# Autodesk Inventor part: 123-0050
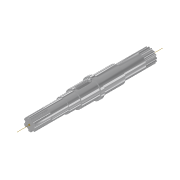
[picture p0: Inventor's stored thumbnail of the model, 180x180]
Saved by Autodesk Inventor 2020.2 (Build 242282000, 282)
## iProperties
+MSCProtocol1+ProtocolID: P00060228124250375
+MSCProtocol2+Protocol: P00060228124250375<@PID>[Version]<@EL>Version=2.0<@EL>[CalcData]<@EL>LastID=8<@EL>Gen=3<@EL>IsMCW=0<@EL>CalcResult=False<@EL>[Files]<@EL>DataFile=SpiData|shaft3
Manager: www.cadconsulting.pl
Company: Fabian Stasiak CAD Consulting
Created: 2004-04
Part Number: 123-0050
Document SubType Name: Modeling
Manufacturer: Standard
Standards Organization: Custom
Description: Wałek
Material: Stal 45
Project: Przekładnia X51
Designer: F.Stasiak
Density: 7.85 g/cm^3
Appearance: Chrom
+MSCFeatProtocols1+FeatNameP00060309102124484: SPLINE2A2
+MSCFeatProtocols2+ProtocolIDP00060309102124484: P00060309102124484
+MSCFeatProtocols3+ProtocolP00060309102124484: P00060309102124484<@PID>[Version]<@EL>Version=2.2<@EL>[Object]<@EL>Description=Kreator wielowypustów ewolwentowych<@EL>ProtID=<@EL>Object=SPLINE2<@EL>[Synchroni
+MSCFeatProtocols4+FeatNameP00060309103342671: N014942B1
+MSCFeatProtocols5+ProtocolIDP00060309103342671: P00060309103342671
+MSCFeatProtocols6+ProtocolP00060309103342671: P00060309103342671<@PID>[Version]<@EL>Version=2.2<@EL>[Synchronize]<@EL>ChangedVars=<@EL>[Calc]<@EL>WizardMode=0<@EL>Version=10.3.272<@EL>Optim=1<@EL>CalcName=S
+MSCFeatProtocols7+FeatNameP00060309103511281: SPLINE2A3
+MSCFeatProtocols8+ProtocolIDP00060309103511281: P00060309103511281
+MSCFeatProtocols9+ProtocolP00060309103511281: P00060309103511281<@PID>[Version]<@EL>Version=2.2<@EL>[Files]<@EL>DataFile=SpiData|Evol<@EL>[Synchronize]<@EL>ChangedVars=<@EL>[Calc]<@EL>WizardMode=0<@EL>Versi
Author: F.Stasiak
Subject: Zbiór ćwiczeń. Autodesk Inventor 2020. Kurs podstawowy
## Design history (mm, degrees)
sketch "Szkic2"
  geometry: L1 (0, 0)-(219, 0) reference; L2 (0, 0)-(0, 11); L3 (0, 11)-(60, 11); L4 (60, 11)-(60, 12.5); L5 (60, 12.5)-(80, 12.5); L6 (80, 12.5)-(80, 15); L7 (80, 15)-(113, 15); L8 (113, 15)-(113, 17.5); L9 (119, 17.5)-(119, 15); L10 (113, 17.5)-(119, 17.5); L11 (159, 15)-(159, 12.5); L12 (119, 15)-(159, 15); L13 (219, 12.5)-(219, 0); L14 (159, 12.5)-(219, 12.5)
  constraints: 28 end point, 7 vertical, 2 horizontal
  dimensions: "d0" = 22 diameter of L3 L1 (derived); "d1" = 25 diameter of L5 L1 (derived); "d2" = 30 diameter of L7 L1 (derived); "d3" = 35 diameter of L10 L1 (derived); "d4" = 30 diameter of L12 L1 (derived); "d5" = 25 diameter of L14 L1 (derived)
revolve "Obrót1" sketch "Szkic2" stored, may be unused: angle "d6" = 0 deg
feature "Keyway1"
node "Oś konstrukcyjna1"
node "Punkt konstrukcyjny1"
sketch "Szkic6"
  geometry: L1 (0, 0.01)-(0, 11.01); L2 (0, 0.01)-(-9.526, 5.51); L3 (-2.5, 10.487)-(-2.5, 8.122); L4 (-7.824, 7.414)-(-5.776, 6.231); L5 (-7.824, 7.414)-(-8.234, 7.304); L6 (-2.5, 10.487)-(-2.2, 10.787); A1 r 0.2 centre (-5.676, 6.404) between (-5.776, 6.231) and (-5.543, 6.255); A2 r 0.2 centre (-2.7, 8.122) between (-2.637, 7.932) and (-2.5, 8.122); A3 r 8.35 centre (0, 0.01) between (-2.637, 7.932) and (-5.543, 6.255); A4 r 11 centre (0, 0.01) between (-2.2, 10.787) and (-8.234, 7.304); A5 r 11 centre (0, 0.01) between (0, 11.01) and (-9.526, 5.51); 1 further point
  constraints: 12 end point, 12 point on circle, 5 centre point, 3 tangent, 2 coincident, 2 equal length, 2 parallel, 2 point on line, 1 concentric, 1 equal radius, 1 vertical
  dimensions: "d83" = 60 deg angle of L1 L2 (derived); "d85" = 2.5 distance between parallel lines of L1 L3 (derived); "d90" = 16.7 diameter of A3 (derived); "d88" = 0.2 radius of A1 (derived); "d87" = 2.5 distance between parallel lines of L2 L4 (derived); "d92" = 0.3 distance from line of L6.end L3 (derived); "d95" = 45 deg angle of L3 L6; "d94" = 45 deg angle of L5 L4; "d96" = 22 diameter of A5 (derived)
feature "N014942B1" sketch "Szkic6"
node "Punkt konstrukcyjny2"
sketch "Szkic7"
  geometry: L1 (0, 0.051)-(0, 12.534); L2 (0, 0.051)-(2.256, 10.664); A1 r 5.355 centre (-3.35, 8.979) between (1.697, 10.768) and (0.654, 12.534); A2 r 10.85 centre (0, 0.051) between (1.697, 10.768) and (2.256, 10.664); A3 r 10.85 centre (0, 0.051) between (2.256, 10.664) and (1.697, 10.768); A4 r 12.5 centre (0, 0.051) between (2.599, 12.278) and (0.654, 12.534); A5 r 10.85 centre (0, 0.051) between (2.808, 10.532) and (2.256, 10.664); A6 r 5.355 centre (6.691, 6.845) between (4.48, 11.721) and (2.808, 10.532); A7 r 12.5 centre (0, 0.051) between (4.48, 11.721) and (2.599, 12.278); 1 further point
  constraints: 14 point on circle, 7 centre point, 5 coincident, 5 end point, 3 symmetric about line, 1 horizontal alignment, 1 point on line, 1 vertical, 3 other
  dimensions: "d98" = 5.35458 radius of A1 (= d99); "d124" = 21.7 diameter of A2 (= d110); "d123" = 3.34956 distance from line of A1.centre L1 (= d120); "d122" = 8.92738 vertical distance of L1.start A1.centre (= d100); "d125" = 12 deg angle of L2 L1 (computed from d105); "d126" = 25 diameter of A4 (= d108)
feature "SPLINE2A3" sketch "Szkic7"
node "Bryła1"
node "Korpusy bryłowe"
node "Korpusy powierzchniowe"
other parameters: "d99" = 5.35458 (computed from d121, d120, d100) [user parameter; used in 1 equation term], "d100" = 8.92738 (computed from d119, d118, d101) [user parameter; used in 4 equation terms], "d101" = 7.53362 (computed from d116, d115, d113, d102) [user parameter; used in 1 equation term], "d102" = -21.09261 (computed from d114, d113, d103) [user parameter; used in 2 equation terms], "d103" = -0.46736 (= d112 - d104) [user parameter; used in 2 equation terms], "d104" = -1.22995 (computed from d107, d105) [user parameter; used in 5 equation terms], "d107" = 11.76667 (= 0.222222 x d110 + 0.277778 x d108) [user parameter; used in 2 equation terms], "d108" = 25 [user parameter; used in 5 equation terms], "d110" = 21.7 [user parameter; used in 5 equation terms], "d112" = -1.69731 (computed from d110, d105) [user parameter; used in 2 equation terms], "d113" = 11.70221 (computed from d107, d105) [user parameter; used in 5 equation terms], "d114" = 10.71642 (computed from d110, d105) [user parameter; used in 2 equation terms], "d115" = 12.48287 (computed from d108, d105) [user parameter; used in 2 equation terms], "d116" = -0.57575 (= d104 - d117) [user parameter; used in 2 equation terms], "d117" = -0.6542 (computed from d108, d105) [user parameter; used in 2 equation terms], "d118" = 22.17973 (computed from d114, d112, d104, d113, d103) [user parameter; used in 2 equation terms], "d119" = 15.45418 (computed from d113, d104, d117, d115, d116) [user parameter; used in 1 equation term], "d120" = 3.34956 (computed from d118, d100, d102) [user parameter; used in 3 equation terms], "d121" = 6.22461 (computed from d104, d120, d113, d100) [user parameter; used in 1 equation term]
